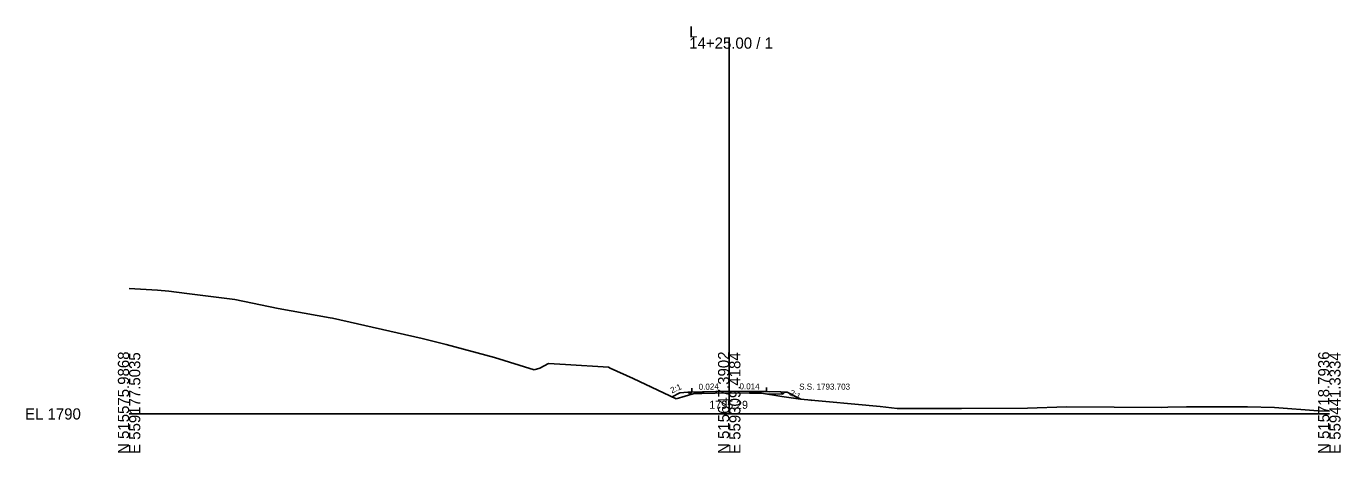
# Model space of a CAD drawing. Extents: x -26 to 1303, y -10 to 9545.
# Drawn here: x 974.3 to 1302.8, y 1490.3 to 1596.9 of the extents above; entities that cross this region are included whole.
import ezdxf

# ---------------------------------------------------------------- set-up
doc = ezdxf.new("R2010")
doc.units = 0
for name, color, linetype in [('Exist Cross Section Cell', 7, 'Continuous'), ('Exist XS Center Line Elevation Label', 7, 'Continuous'), ('Exist XS Ground Line', 7, 'Continuous'), ('Prop XS Ditch Slope Text', 7, 'Continuous'), ('Prop XS Dump Level', 7, 'Continuous'), ('Prop XS EOT Tick Mark', 7, 'Continuous'), ('Prop XS Finish Grade', 7, 'Continuous'), ('Prop XS Finish Grade Earthwork', 7, 'Continuous'), ('Prop XS Finish Grade Paved Shoulder', 7, 'Continuous'), ('Prop XS Finish Grade Pavement', 7, 'Continuous'), ('Prop XS Pvmt Edge Slope', 7, 'Continuous'), ('Prop XS SE Text', 7, 'Continuous'), ('Prop XS SS Elevation Text', 7, 'Continuous'), ('Prop XS Subgrade Earthwork', 7, 'Continuous')]:
    doc.layers.add(name, color=color, linetype=linetype)

msp = doc.modelspace()

# ---------------------------------------------------------------- linework, layer by layer
at = {"layer": 'Exist Cross Section Cell'}
for p, q in [((1150, 1500), (1150, 1594.09)), ((1000, 1500), (1150, 1500)), ((1150, 1500), (1300, 1500))]:
    msp.add_line(p, q, dxfattribs=at)
at = {"layer": 'Exist XS Ground Line'}
for p, q in [((1000, 1531.36), (1007.07, 1530.93)), ((1007.07, 1530.93), (1009.95, 1530.72)), ((1009.95, 1530.72), (1014.46, 1530.13)), ((1014.46, 1530.13), (1026.44, 1528.64)), ((1026.44, 1528.64), (1037.24, 1526.38)), ((1037.24, 1526.38), (1050.28, 1524.01)), ((1050.28, 1524.01), (1050.85, 1523.91)), ((1050.85, 1523.91), (1073.25, 1518.82)), ((1073.25, 1518.82), (1079.25, 1517.39)), ((1079.25, 1517.39), (1091.37, 1514.14)), ((1091.37, 1514.14), (1101.23, 1511.03)), ((1101.23, 1511.03), (1102.63, 1511.43)), ((1102.63, 1511.43), (1104.82, 1512.57)), ((1104.82, 1512.57), (1109.04, 1512.32)), ((1109.04, 1512.32), (1119.85, 1511.67)), ((1119.85, 1511.67), (1120.25, 1511.48)), ((1120.25, 1511.48), (1126, 1508.86)), ((1126, 1508.86), (1136.72, 1503.8)), ((1138.95, 1504.43), (1141.28, 1505.1)), ((1141.28, 1505.1), (1143.15, 1505.13)), ((1143.15, 1505.13), (1149.93, 1505.29)), ((1149.93, 1505.29), (1155.11, 1505.22)), ((1155.11, 1505.22), (1158.09, 1505.18)), ((1158.09, 1505.18), (1163.11, 1504.32)), ((1136.72, 1503.8), (1138.95, 1504.43)), ((1163.11, 1504.32), (1167.8, 1503.71)), ((1167.8, 1503.71), (1187.7, 1501.82)), ((1187.7, 1501.82), (1191.97, 1501.34)), ((1198.37, 1501.39), (1203.13, 1501.39)), ((1203.13, 1501.39), (1208.02, 1501.33)), ((1208.02, 1501.33), (1224.56, 1501.47)), ((1224.56, 1501.47), (1234.3, 1501.8)), ((1234.3, 1501.8), (1258.15, 1501.64)), ((1258.15, 1501.64), (1259.67, 1501.68)), ((1259.67, 1501.68), (1264.32, 1501.77)), ((1264.32, 1501.77), (1279.57, 1501.8)), ((1279.57, 1501.8), (1286.29, 1501.62)), ((1286.29, 1501.62), (1297.22, 1500.79)), ((1191.97, 1501.34), (1192.37, 1501.35)), ((1192.37, 1501.35), (1193.71, 1501.35)), ((1193.71, 1501.35), (1198.37, 1501.39)), ((1297.22, 1500.79), (1300, 1500.71))]:
    msp.add_line(p, q, dxfattribs=at)
at = {"layer": 'Prop XS Dump Level'}
for p, q in [((1140, 1505.46), (1150, 1505.71)), ((1150, 1505.71), (1160, 1505.56))]:
    msp.add_line(p, q, dxfattribs=at)
at = {"layer": 'Prop XS EOT Tick Mark'}
for p, q in [((1140.69, 1505.48), (1140.69, 1506.48)), ((1159.33, 1505.57), (1159.33, 1506.57))]:
    msp.add_line(p, q, dxfattribs=at)
at = {"layer": 'Prop XS Finish Grade'}
for p, q in [((1140.69, 1505.48), (1139.66, 1505.4)), ((1162.88, 1505.52), (1163.9, 1505.45))]:
    msp.add_line(p, q, dxfattribs=at)
at = {"layer": 'Prop XS Finish Grade Earthwork'}
for p, q in [((1137.69, 1505.24), (1135.74, 1504.26)), ((1139.66, 1505.4), (1137.69, 1505.24)), ((1163.9, 1505.45), (1164.45, 1505.41)), ((1164.45, 1505.41), (1167.86, 1503.7))]:
    msp.add_line(p, q, dxfattribs=at)
at = {"layer": 'Prop XS Finish Grade Paved Shoulder'}
msp.add_line((1159.33, 1505.57), (1162.88, 1505.52), dxfattribs=at)
at = {"layer": 'Prop XS Finish Grade Pavement'}
for p, q in [((1140.69, 1505.48), (1150, 1505.71)), ((1150, 1505.71), (1159.33, 1505.57))]:
    msp.add_line(p, q, dxfattribs=at)
at = {"layer": 'Prop XS Pvmt Edge Slope'}
for p, q in [((1140.69, 1505.48), (1140.13, 1504.92)), ((1162.88, 1505.52), (1163.43, 1504.97))]:
    msp.add_line(p, q, dxfattribs=at)
at = {"layer": 'Prop XS Subgrade Earthwork'}
for p, q in [((1140.13, 1504.92), (1139.66, 1505.4)), ((1140.69, 1504.94), (1140.13, 1504.93)), ((1140.69, 1504.94), (1140.69, 1504.75)), ((1159.33, 1505.03), (1159.33, 1504.97)), ((1159.33, 1505.03), (1163.43, 1504.97)), ((1163.43, 1504.97), (1163.9, 1505.45))]:
    msp.add_line(p, q, dxfattribs=at)

# ---------------------------------------------------------------- texts
at = {"layer": 'Exist Cross Section Cell'}
for s, p in [('L', (1140, 1594.09)), ('14+25.00 / 1', (1140, 1591.29)), ('EL 1790', (974, 1498.6))]:
    msp.add_text(s, height=2.8, dxfattribs=at).set_placement(p)
for s, p in [('N 515575.9868', (1000, 1490)), ('E 559177.5035', (1002.8, 1490)), ('N 515647.3902', (1150, 1490)), ('E 559309.4184', (1152.8, 1490)), ('N 515718.7936', (1300, 1490)), ('E 559441.3334', (1302.8, 1490))]:
    msp.add_text(s, height=2.8, rotation=90, dxfattribs=at).set_placement(p)
at = {"layer": 'Exist XS Center Line Elevation Label'}
msp.add_text('1795.29', height=2, dxfattribs=at).set_placement((1145.02, 1501.29))
at = {"layer": 'Prop XS Ditch Slope Text'}
for rotation, p in [(23.9713, (1135.69, 1505.12)), (333.4349, (1164.92, 1504.79))]:
    msp.add_text('2:1', height=1.5, rotation=rotation, dxfattribs=at).set_placement(p)
at = {"layer": 'Prop XS Dump Level'}
for s, height, p in [('Eop', 0.3, (1130, 1506.67)), ('Case1', 0.04, (1137, 1505.18)), ('Case1', 0.04, (1163, 1505.3)), ('Eop', 0.3, (1170, 1503.2))]:
    msp.add_text(s, height=height, dxfattribs=at).set_placement(p)
at = {"layer": 'Prop XS SE Text'}
for s, rotation, p in [('0.024', 1.3825, (1142.39, 1506.02)), ('0.014', 359.1903, (1152.56, 1506.17))]:
    msp.add_text(s, height=1.5, rotation=rotation, dxfattribs=at).set_placement(p)
at = {"layer": 'Prop XS SS Elevation Text'}
msp.add_text('S.S. 1793.703', height=1.5, dxfattribs=at).set_placement((1167.49, 1506.08))

doc.saveas('drawing.dxf')
